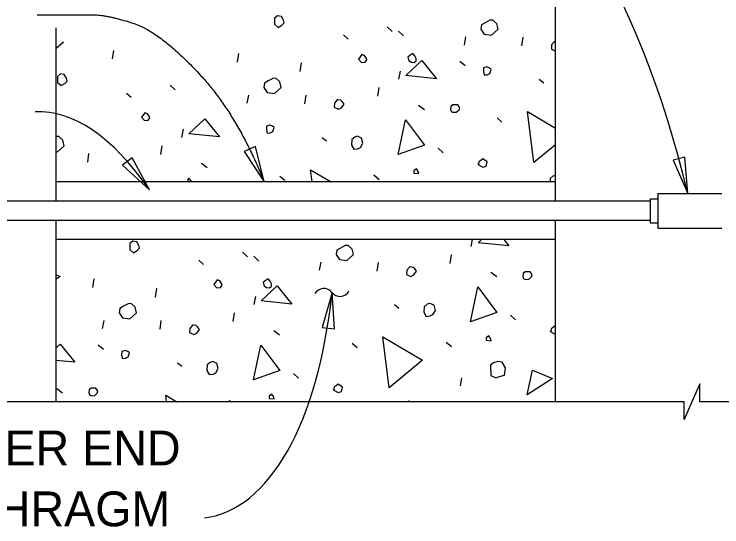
# Model space of a CAD drawing. Extents: x -1660015.2 to -1659984.9, y 2580594.2 to 2580616.7.
# Drawn here: x -1659992.865 to -1659989.794, y 2580607.364 to 2580609.587 of the extents above; entities that cross this region are included whole.
import ezdxf

# ---------------------------------------------------------------- set-up
doc = ezdxf.new("R2010")
doc.units = 0
for name, color, linetype in [('Default', 7, 'Continuous'), ('Miscellaneous', 7, 'Continuous'), ('Miscellaneous3', 7, 'Continuous'), ('SheetLines_dp', 7, 'Continuous')]:
    doc.layers.add(name, color=color, linetype=linetype)

msp = doc.modelspace()

# ---------------------------------------------------------------- linework, layer by layer
at = {"layer": 'Default'}
for p, q in [((-1659990.0713, 2580608.8094), (-1659989.7938, 2580608.8094)), ((-1659990.0713, 2580608.8093), (-1659990.0713, 2580608.6595)), ((-1659990.1046, 2580608.776), (-1659994.2928, 2580608.776)), ((-1659990.1046, 2580608.7865), (-1659990.1046, 2580608.6823)), ((-1659990.1046, 2580608.7865), (-1659990.0713, 2580608.7865)), ((-1659990.1046, 2580608.6927), (-1659994.2928, 2580608.6927)), ((-1659990.1046, 2580608.6823), (-1659990.0713, 2580608.6823)), ((-1659990.0713, 2580608.6595), (-1659989.7938, 2580608.6595))]:
    msp.add_line(p, q, dxfattribs=at)
at = {"layer": 'Miscellaneous'}
for p, q in [((-1659991.2454, 2580609.5321), (-1659991.2244, 2580609.5119)), ((-1659991.1965, 2580609.5141), (-1659991.1756, 2580609.4939)), ((-1659991.4352, 2580609.4968), (-1659991.4149, 2580609.4789)), ((-1659990.9111, 2580609.4534), (-1659990.905, 2580609.4887)), ((-1659990.6618, 2580609.4504), (-1659990.6564, 2580609.4881)), ((-1659992.4377, 2580609.3938), (-1659992.4316, 2580609.4291)), ((-1659991.8953, 2580609.3787), (-1659991.8899, 2580609.4164)), ((-1659990.9312, 2580609.3834), (-1659990.9078, 2580609.3638)), ((-1659991.6229, 2580609.3378), (-1659991.6175, 2580609.3755)), ((-1659991.1948, 2580609.305), (-1659991.1888, 2580609.3402)), ((-1659990.5866, 2580609.3049), (-1659990.5669, 2580609.2894)), ((-1659992.1871, 2580609.2798), (-1659992.1662, 2580609.2595)), ((-1659991.2864, 2580609.2312), (-1659991.281, 2580609.2689)), ((-1659992.377, 2580609.2444), (-1659992.3567, 2580609.2266)), ((-1659991.8529, 2580609.2011), (-1659991.8468, 2580609.2364)), ((-1659991.6036, 2580609.198), (-1659991.5982, 2580609.2357)), ((-1659991.1105, 2580609.193), (-1659991.0847, 2580609.174)), ((-1659990.7693, 2580609.1369), (-1659990.749, 2580609.119)), ((-1659992.1366, 2580609.0526), (-1659992.1305, 2580609.0879)), ((-1659991.5284, 2580609.0525), (-1659991.5087, 2580609.0371)), ((-1659992.2282, 2580608.9789), (-1659992.2227, 2580609.0166)), ((-1659992.5454, 2580608.9457), (-1659992.5399, 2580608.9834)), ((-1659991.0243, 2580609.0064), (-1659991.0033, 2580608.9862)), ((-1659992.0523, 2580608.9406), (-1659992.0265, 2580608.9216)), ((-1659991.3037, 2580608.8901), (-1659991.2803, 2580608.8705)), ((-1659990.5159, 2580608.8593), (-1659992.6826, 2580608.8593)), ((-1659991.7111, 2580608.8845), (-1659991.6908, 2580608.8667)), ((-1659990.5159, 2580608.6094), (-1659992.6826, 2580608.6094)), ((-1659990.8809, 2580608.5801), (-1659990.8759, 2580608.6094)), ((-1659991.8732, 2580608.5549), (-1659991.8523, 2580608.5346)), ((-1659992.063, 2580608.5196), (-1659992.0427, 2580608.5017)), ((-1659991.8244, 2580608.5369), (-1659991.8035, 2580608.5166)), ((-1659990.9725, 2580608.5064), (-1659990.967, 2580608.5441)), ((-1659991.539, 2580608.4762), (-1659991.5329, 2580608.5115)), ((-1659991.2897, 2580608.4731), (-1659991.2843, 2580608.5108)), ((-1659990.7966, 2580608.4681), (-1659990.7708, 2580608.4491)), ((-1659992.5232, 2580608.4014), (-1659992.5177, 2580608.4391)), ((-1659992.2508, 2580608.3605), (-1659992.2454, 2580608.3982)), ((-1659991.8227, 2580608.3277), (-1659991.8166, 2580608.363)), ((-1659991.2145, 2580608.3276), (-1659991.1948, 2580608.3122)), ((-1659991.9143, 2580608.254), (-1659991.9088, 2580608.2917)), ((-1659990.7104, 2580608.2815), (-1659990.6894, 2580608.2613)), ((-1659992.4808, 2580608.2239), (-1659992.4747, 2580608.2591)), ((-1659992.2315, 2580608.2208), (-1659992.226, 2580608.2585)), ((-1659991.7384, 2580608.2157), (-1659991.7126, 2580608.1968)), ((-1659992.5008, 2580608.1538), (-1659992.4774, 2580608.1342)), ((-1659991.3972, 2580608.1596), (-1659991.3769, 2580608.1418)), ((-1659990.9898, 2580608.1653), (-1659990.9664, 2580608.1456)), ((-1659992.1562, 2580608.0753), (-1659992.1366, 2580608.0599)), ((-1659991.6521, 2580608.0292), (-1659991.6312, 2580608.0089)), ((-1659990.9284, 2580607.9747), (-1659990.9223, 2580608.0099)), ((-1659992.6801, 2580607.9634), (-1659992.6543, 2580607.9444)), ((-1659992.339, 2580607.9073), (-1659992.3382, 2580607.9066)), ((-1659991.9316, 2580607.9129), (-1659991.9241, 2580607.9066))]:
    msp.add_line(p, q, dxfattribs=at)
for points in [[(-1659991.7346, 2580609.5615), (-1659991.7349, 2580609.5433), (-1659991.7183, 2580609.5296), (-1659991.7027, 2580609.539), (-1659991.6926, 2580609.5495), (-1659991.6958, 2580609.5615), (-1659991.7052, 2580609.5771), (-1659991.7216, 2580609.5805), (-1659991.7342, 2580609.5694), (-1659991.7346, 2580609.5615)], [(-1659990.8389, 2580609.522), (-1659990.8252, 2580609.4998), (-1659990.793, 2580609.4955), (-1659990.7637, 2580609.5214), (-1659990.7702, 2580609.5456), (-1659990.7874, 2580609.5617), (-1659990.8001, 2580609.5608), (-1659990.8206, 2580609.5502), (-1659990.8362, 2580609.5408), (-1659990.8389, 2580609.522)], [(-1659992.6504, 2580609.4652), (-1659992.6826, 2580609.4387)], [(-1659990.5333, 2580609.4537), (-1659990.5336, 2580609.4355), (-1659990.5159, 2580609.4273)], [(-1659990.5159, 2580609.4684), (-1659990.5166, 2580609.4686), (-1659990.5214, 2580609.4673), (-1659990.5333, 2580609.4537)], [(-1659991.371, 2580609.3923), (-1659991.3568, 2580609.378), (-1659991.3416, 2580609.3795), (-1659991.3339, 2580609.3893), (-1659991.3352, 2580609.3942), (-1659991.3439, 2580609.4074), (-1659991.3555, 2580609.412), (-1659991.3633, 2580609.4022), (-1659991.371, 2580609.3923)], [(-1659991.1519, 2580609.3863), (-1659991.1421, 2580609.3786), (-1659991.1287, 2580609.377), (-1659991.1204, 2580609.3844), (-1659991.1206, 2580609.3947), (-1659991.1262, 2580609.4062), (-1659991.1343, 2580609.4169), (-1659991.1475, 2580609.4082), (-1659991.1558, 2580609.4008), (-1659991.1519, 2580609.3863)], [(-1659991.1654, 2580609.3206), (-1659991.0949, 2580609.3861), (-1659991.0324, 2580609.3071), (-1659991.1654, 2580609.3206)], [(-1659990.8285, 2580609.3384), (-1659990.8246, 2580609.3239), (-1659990.8119, 2580609.3247), (-1659990.8005, 2580609.3304), (-1659990.7947, 2580609.3475), (-1659990.8015, 2580609.3534), (-1659990.8131, 2580609.3581), (-1659990.8276, 2580609.3542), (-1659990.8285, 2580609.3384)], [(-1659992.6764, 2580609.3091), (-1659992.6767, 2580609.2909), (-1659992.6601, 2580609.2773), (-1659992.6445, 2580609.2866), (-1659992.6344, 2580609.2971), (-1659992.6376, 2580609.3092), (-1659992.647, 2580609.3248), (-1659992.6634, 2580609.3282), (-1659992.6759, 2580609.317), (-1659992.6764, 2580609.3091)], [(-1659991.7807, 2580609.2696), (-1659991.767, 2580609.2474), (-1659991.7347, 2580609.2431), (-1659991.7055, 2580609.2691), (-1659991.7119, 2580609.2932), (-1659991.7292, 2580609.3093), (-1659991.7419, 2580609.3085), (-1659991.7623, 2580609.2978), (-1659991.778, 2580609.2885), (-1659991.7807, 2580609.2696)], [(-1659991.4751, 2580609.2014), (-1659991.4754, 2580609.1832), (-1659991.4577, 2580609.175), (-1659991.4438, 2580609.1813), (-1659991.4326, 2580609.1973), (-1659991.4406, 2580609.208), (-1659991.4474, 2580609.214), (-1659991.4584, 2580609.2162), (-1659991.4632, 2580609.2149), (-1659991.4751, 2580609.2014)], [(-1659990.9687, 2580609.1662), (-1659990.9626, 2580609.1627), (-1659990.9468, 2580609.1618), (-1659990.9343, 2580609.1729), (-1659990.9314, 2580609.1814), (-1659990.9401, 2580609.1946), (-1659990.9607, 2580609.1943), (-1659990.9691, 2580609.1869), (-1659990.9713, 2580609.1759), (-1659990.9687, 2580609.1662)], [(-1659990.609, 2580608.9443), (-1659990.637, 2580609.1645), (-1659990.5159, 2580609.0932)], [(-1659992.3127, 2580609.14), (-1659992.2986, 2580609.1257), (-1659992.2834, 2580609.1271), (-1659992.2757, 2580609.137), (-1659992.277, 2580609.1418), (-1659992.2857, 2580609.155), (-1659992.2973, 2580609.1597), (-1659992.305, 2580609.1498), (-1659992.3127, 2580609.14)], [(-1659992.1072, 2580609.0683), (-1659992.0367, 2580609.1337), (-1659991.9741, 2580609.0547), (-1659992.1072, 2580609.0683)], [(-1659991.7703, 2580609.0861), (-1659991.7664, 2580609.0716), (-1659991.7537, 2580609.0724), (-1659991.7423, 2580609.078), (-1659991.7365, 2580609.0951), (-1659991.7433, 2580609.1011), (-1659991.7549, 2580609.1057), (-1659991.7694, 2580609.1018), (-1659991.7703, 2580609.0861)], [(-1659991.1978, 2580608.978), (-1659991.1658, 2580609.129), (-1659991.0845, 2580609.0188), (-1659991.1978, 2580608.978)], [(-1659992.6826, 2580608.9916), (-1659992.6765, 2580608.9908), (-1659992.6472, 2580609.0167), (-1659992.6537, 2580609.0409), (-1659992.671, 2580609.057), (-1659992.6826, 2580609.0562)], [(-1659991.3991, 2580609.0432), (-1659991.4005, 2580609.0195), (-1659991.3905, 2580609.0015), (-1659991.3729, 2580609.0036), (-1659991.3615, 2580609.0092), (-1659991.3509, 2580609.0276), (-1659991.3567, 2580609.0493), (-1659991.3744, 2580609.0575), (-1659991.3865, 2580609.0543), (-1659991.3991, 2580609.0432)], [(-1659990.5159, 2580609.0211), (-1659990.609, 2580608.9443)], [(-1659990.8496, 2580608.9342), (-1659990.8312, 2580608.9236), (-1659990.8168, 2580608.9274), (-1659990.8116, 2580608.9469), (-1659990.8306, 2580608.96), (-1659990.839, 2580608.9525), (-1659990.848, 2580608.9475), (-1659990.8496, 2580608.9342), (-1659990.8509, 2580608.939)], [(-1659991.1298, 2580608.8979), (-1659991.1085, 2580608.8959), (-1659991.1111, 2580608.9055), (-1659991.1192, 2580608.9163), (-1659991.13, 2580608.9082), (-1659991.1298, 2580608.8979)], [(-1659991.5721, 2580608.8593), (-1659991.5788, 2580608.9122), (-1659991.4891, 2580608.8593)], [(-1659990.5159, 2580608.8841), (-1659990.5262, 2580608.8862), (-1659990.5387, 2580608.8751), (-1659990.5392, 2580608.8672)], [(-1659992.1113, 2580608.8593), (-1659992.1076, 2580608.8766), (-1659992.0948, 2580608.8593)], [(-1659990.5392, 2580608.8672), (-1659990.5393, 2580608.8593)], [(-1659990.8515, 2580608.5957), (-1659990.8367, 2580608.6094)], [(-1659990.74, 2580608.6094), (-1659990.7184, 2580608.5822), (-1659990.8515, 2580608.5957)], [(-1659992.3625, 2580608.5843), (-1659992.3628, 2580608.5661), (-1659992.3462, 2580608.5524), (-1659992.3306, 2580608.5618), (-1659992.3205, 2580608.5722), (-1659992.3237, 2580608.5843), (-1659992.333, 2580608.5999), (-1659992.3495, 2580608.6033), (-1659992.362, 2580608.5921), (-1659992.3625, 2580608.5843)], [(-1659991.4668, 2580608.5447), (-1659991.453, 2580608.5225), (-1659991.4208, 2580608.5182), (-1659991.3915, 2580608.5442), (-1659991.398, 2580608.5683), (-1659991.4153, 2580608.5844), (-1659991.428, 2580608.5836), (-1659991.4484, 2580608.573), (-1659991.464, 2580608.5636), (-1659991.4668, 2580608.5447)], [(-1659991.1612, 2580608.4765), (-1659991.1615, 2580608.4583), (-1659991.1438, 2580608.4501), (-1659991.1299, 2580608.4564), (-1659991.1187, 2580608.4724), (-1659991.1267, 2580608.4832), (-1659991.1335, 2580608.4891), (-1659991.1444, 2580608.4913), (-1659991.1493, 2580608.4901), (-1659991.1612, 2580608.4765)], [(-1659992.6826, 2580608.456), (-1659992.6653, 2580608.4488), (-1659992.6826, 2580608.4376)], [(-1659990.6548, 2580608.4414), (-1659990.6487, 2580608.4378), (-1659990.6329, 2580608.4369), (-1659990.6204, 2580608.448), (-1659990.6175, 2580608.4565), (-1659990.6262, 2580608.4697), (-1659990.6468, 2580608.4694), (-1659990.6552, 2580608.462), (-1659990.6574, 2580608.451), (-1659990.6548, 2580608.4414)], [(-1659991.9988, 2580608.4151), (-1659991.9846, 2580608.4008), (-1659991.9695, 2580608.4023), (-1659991.9618, 2580608.4121), (-1659991.9631, 2580608.4169), (-1659991.9718, 2580608.4301), (-1659991.9834, 2580608.4348), (-1659991.9911, 2580608.425), (-1659991.9988, 2580608.4151)], [(-1659991.7798, 2580608.4091), (-1659991.77, 2580608.4014), (-1659991.7566, 2580608.3998), (-1659991.7482, 2580608.4072), (-1659991.7484, 2580608.4175), (-1659991.7541, 2580608.4289), (-1659991.7621, 2580608.4397), (-1659991.7753, 2580608.431), (-1659991.7837, 2580608.4236), (-1659991.7798, 2580608.4091)], [(-1659991.7933, 2580608.3434), (-1659991.7228, 2580608.4088), (-1659991.6602, 2580608.3299), (-1659991.7933, 2580608.3434)], [(-1659990.8839, 2580608.2532), (-1659990.8519, 2580608.4041), (-1659990.7706, 2580608.2939), (-1659990.8839, 2580608.2532)], [(-1659992.4085, 2580608.2924), (-1659992.3948, 2580608.2702), (-1659992.3626, 2580608.2659), (-1659992.3333, 2580608.2918), (-1659992.3398, 2580608.316), (-1659992.357, 2580608.3321), (-1659992.3698, 2580608.3313), (-1659992.3902, 2580608.3206), (-1659992.4058, 2580608.3112), (-1659992.4085, 2580608.2924)], [(-1659991.0851, 2580608.3183), (-1659991.0866, 2580608.2946), (-1659991.0766, 2580608.2766), (-1659991.059, 2580608.2787), (-1659991.0476, 2580608.2844), (-1659991.037, 2580608.3027), (-1659991.0428, 2580608.3245), (-1659991.0605, 2580608.3327), (-1659991.0726, 2580608.3294), (-1659991.0851, 2580608.3183)], [(-1659992.103, 2580608.2242), (-1659992.1033, 2580608.206), (-1659992.0855, 2580608.1978), (-1659992.0717, 2580608.2041), (-1659992.0604, 2580608.22), (-1659992.0685, 2580608.2308), (-1659992.0753, 2580608.2368), (-1659992.0862, 2580608.239), (-1659992.0911, 2580608.2377), (-1659992.103, 2580608.2242)], [(-1659990.5159, 2580608.2345), (-1659990.5167, 2580608.2351), (-1659990.5251, 2580608.2277), (-1659990.5341, 2580608.2227), (-1659990.5357, 2580608.2093), (-1659990.537, 2580608.2141)], [(-1659991.2369, 2580607.9671), (-1659991.2649, 2580608.1873), (-1659991.0928, 2580608.0859), (-1659991.2369, 2580607.9671)], [(-1659990.8159, 2580608.173), (-1659990.7946, 2580608.171), (-1659990.7972, 2580608.1806), (-1659990.8053, 2580608.1914), (-1659990.816, 2580608.1834), (-1659990.8159, 2580608.173)], [(-1659990.5357, 2580608.2093), (-1659990.5173, 2580608.1987), (-1659990.5159, 2580608.1991)], [(-1659992.6826, 2580608.1398), (-1659992.6646, 2580608.1565), (-1659992.602, 2580608.0775), (-1659992.6826, 2580608.0857)], [(-1659991.8257, 2580608.0008), (-1659991.7937, 2580608.1517), (-1659991.7124, 2580608.0415), (-1659991.8257, 2580608.0008)], [(-1659992.3982, 2580608.1088), (-1659992.3943, 2580608.0943), (-1659992.3816, 2580608.0952), (-1659992.3701, 2580608.1008), (-1659992.3644, 2580608.1179), (-1659992.3711, 2580608.1238), (-1659992.3827, 2580608.1285), (-1659992.3972, 2580608.1246), (-1659992.3982, 2580608.1088)], [(-1659992.0269, 2580608.066), (-1659992.0283, 2580608.0423), (-1659992.0183, 2580608.0243), (-1659992.0008, 2580608.0264), (-1659991.9894, 2580608.032), (-1659991.9787, 2580608.0504), (-1659991.9846, 2580608.0721), (-1659992.0023, 2580608.0803), (-1659992.0144, 2580608.0771), (-1659992.0269, 2580608.066)], [(-1659990.7971, 2580608.0642), (-1659990.7957, 2580608.0206), (-1659990.7749, 2580608.0106), (-1659990.7629, 2580608.0138), (-1659990.7363, 2580608.021), (-1659990.732, 2580608.0532), (-1659990.7463, 2580608.0778), (-1659990.7652, 2580608.0805), (-1659990.7845, 2580608.0753), (-1659990.7971, 2580608.0642)], [(-1659990.6384, 2580607.9359), (-1659990.6154, 2580608.043), (-1659990.5281, 2580608.0069), (-1659990.6384, 2580607.9359)], [(-1659992.5384, 2580607.9367), (-1659992.5323, 2580607.9331), (-1659992.5165, 2580607.9322), (-1659992.5039, 2580607.9433), (-1659992.501, 2580607.9519), (-1659992.5098, 2580607.965), (-1659992.5304, 2580607.9647), (-1659992.5387, 2580607.9573), (-1659992.541, 2580607.9463), (-1659992.5384, 2580607.9367)], [(-1659991.4775, 2580607.9569), (-1659991.4591, 2580607.9463), (-1659991.4446, 2580607.9502), (-1659991.4395, 2580607.9697), (-1659991.4585, 2580607.9827), (-1659991.4669, 2580607.9753), (-1659991.4759, 2580607.9703), (-1659991.4775, 2580607.9569), (-1659991.4788, 2580607.9618)], [(-1659992.203, 2580607.9066), (-1659992.2066, 2580607.935), (-1659992.1585, 2580607.9066)], [(-1659991.7576, 2580607.9207), (-1659991.7364, 2580607.9186), (-1659991.739, 2580607.9283), (-1659991.747, 2580607.9391), (-1659991.7578, 2580607.931), (-1659991.7576, 2580607.9207)], [(-1659991.1424, 2580607.9066), (-1659991.1541, 2580607.909), (-1659991.1567, 2580607.9066)]]:
    msp.add_lwpolyline(points, dxfattribs=at)
at = {"layer": 'Miscellaneous3'}
for p, q in [((-1659990.5159, 2580608.776), (-1659990.5159, 2580612.362)), ((-1659992.6826, 2580608.776), (-1659992.6826, 2580609.5276)), ((-1659992.6826, 2580607.9066), (-1659992.6826, 2580608.6927)), ((-1659990.5159, 2580607.9066), (-1659990.5159, 2580608.6927))]:
    msp.add_line(p, q, dxfattribs=at)
at = {"layer": 'SheetLines_dp'}
for points in [[(-1659991.7792, 2580608.8593), (-1659991.8176, 2580609.013), (-1659991.8661, 2580608.9918)], [(-1659992.2779, 2580608.8247), (-1659992.3528, 2580608.9644), (-1659992.3946, 2580608.9319)], [(-1659989.9407, 2580608.8094), (-1659989.9543, 2580608.9673), (-1659990.0056, 2580608.954)], [(-1659991.4851, 2580608.3803), (-1659991.5277, 2580608.2277), (-1659991.4751, 2580608.2222)]]:
    msp.add_lwpolyline(points, close=True, dxfattribs=at)
msp.add_lwpolyline([(-1659986.5682, 2580607.9066), (-1659989.8898, 2580607.9066), (-1659989.8898, 2580607.9841), (-1659989.9235, 2580607.9066), (-1659989.9573, 2580607.8291), (-1659989.9573, 2580607.9066), (-1659994.3703, 2580607.9066)], dxfattribs=at)
for centre, start, end in [((-1659991.5208, 2580608.3527), 38.1822, 149.9094), ((-1659991.4505, 2580608.408), 218.1822, 329.9094)]:
    msp.add_arc(centre, 0.0447, start, end, dxfattribs=at)
for centre, major_axis, ratio, start_param, end_param in [((-1659990.9235, 2580606.5865), (-0.0172, -3.681), 0.331804, 2.220726, 3.141608), ((-1659992.6194, 2580605.9759), (0.1544, -3.1879), 0.324138, 2.660287, 3.141582), ((-1659992.2289, 2580609.0244), (-0.1909, 1.6213), 0.453794, 3.141619, 4.251067)]:
    msp.add_ellipse(centre, major_axis=major_axis, ratio=ratio, start_param=start_param, end_param=end_param, dxfattribs=at)
msp.add_open_spline([(-1659992.7644, 2580609.5842), (-1659992.5884, 2580609.5842), (-1659992.4576, 2580609.5842), (-1659992.2313, 2580609.5087), (-1659991.8994, 2580609.1566), (-1659991.7792, 2580608.8593)], degree=2, dxfattribs=at)

# ---------------------------------------------------------------- texts
for s, p in [('GIRDER END', (-1659993.4117, 2580607.6299)), ('DIAPHRAGM', (-1659993.4117, 2580607.3659))]:
    msp.add_text(s, height=0.1512, dxfattribs=at).set_placement(p)

doc.saveas('drawing.dxf')
